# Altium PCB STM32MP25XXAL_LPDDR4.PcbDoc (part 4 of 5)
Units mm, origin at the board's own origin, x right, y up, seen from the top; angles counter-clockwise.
Board outline 125 x 95 mm, 6 copper layers (Top Layer, Signal Layer 1, Signal Layer 2, Signal Layer 3, Signal Layer 4, Bottom Layer), stack 1.403 mm thick; 182 components, 297 nets, 1131 pads, 958 vias.
Unrouted connection lines stored in the file: 5.
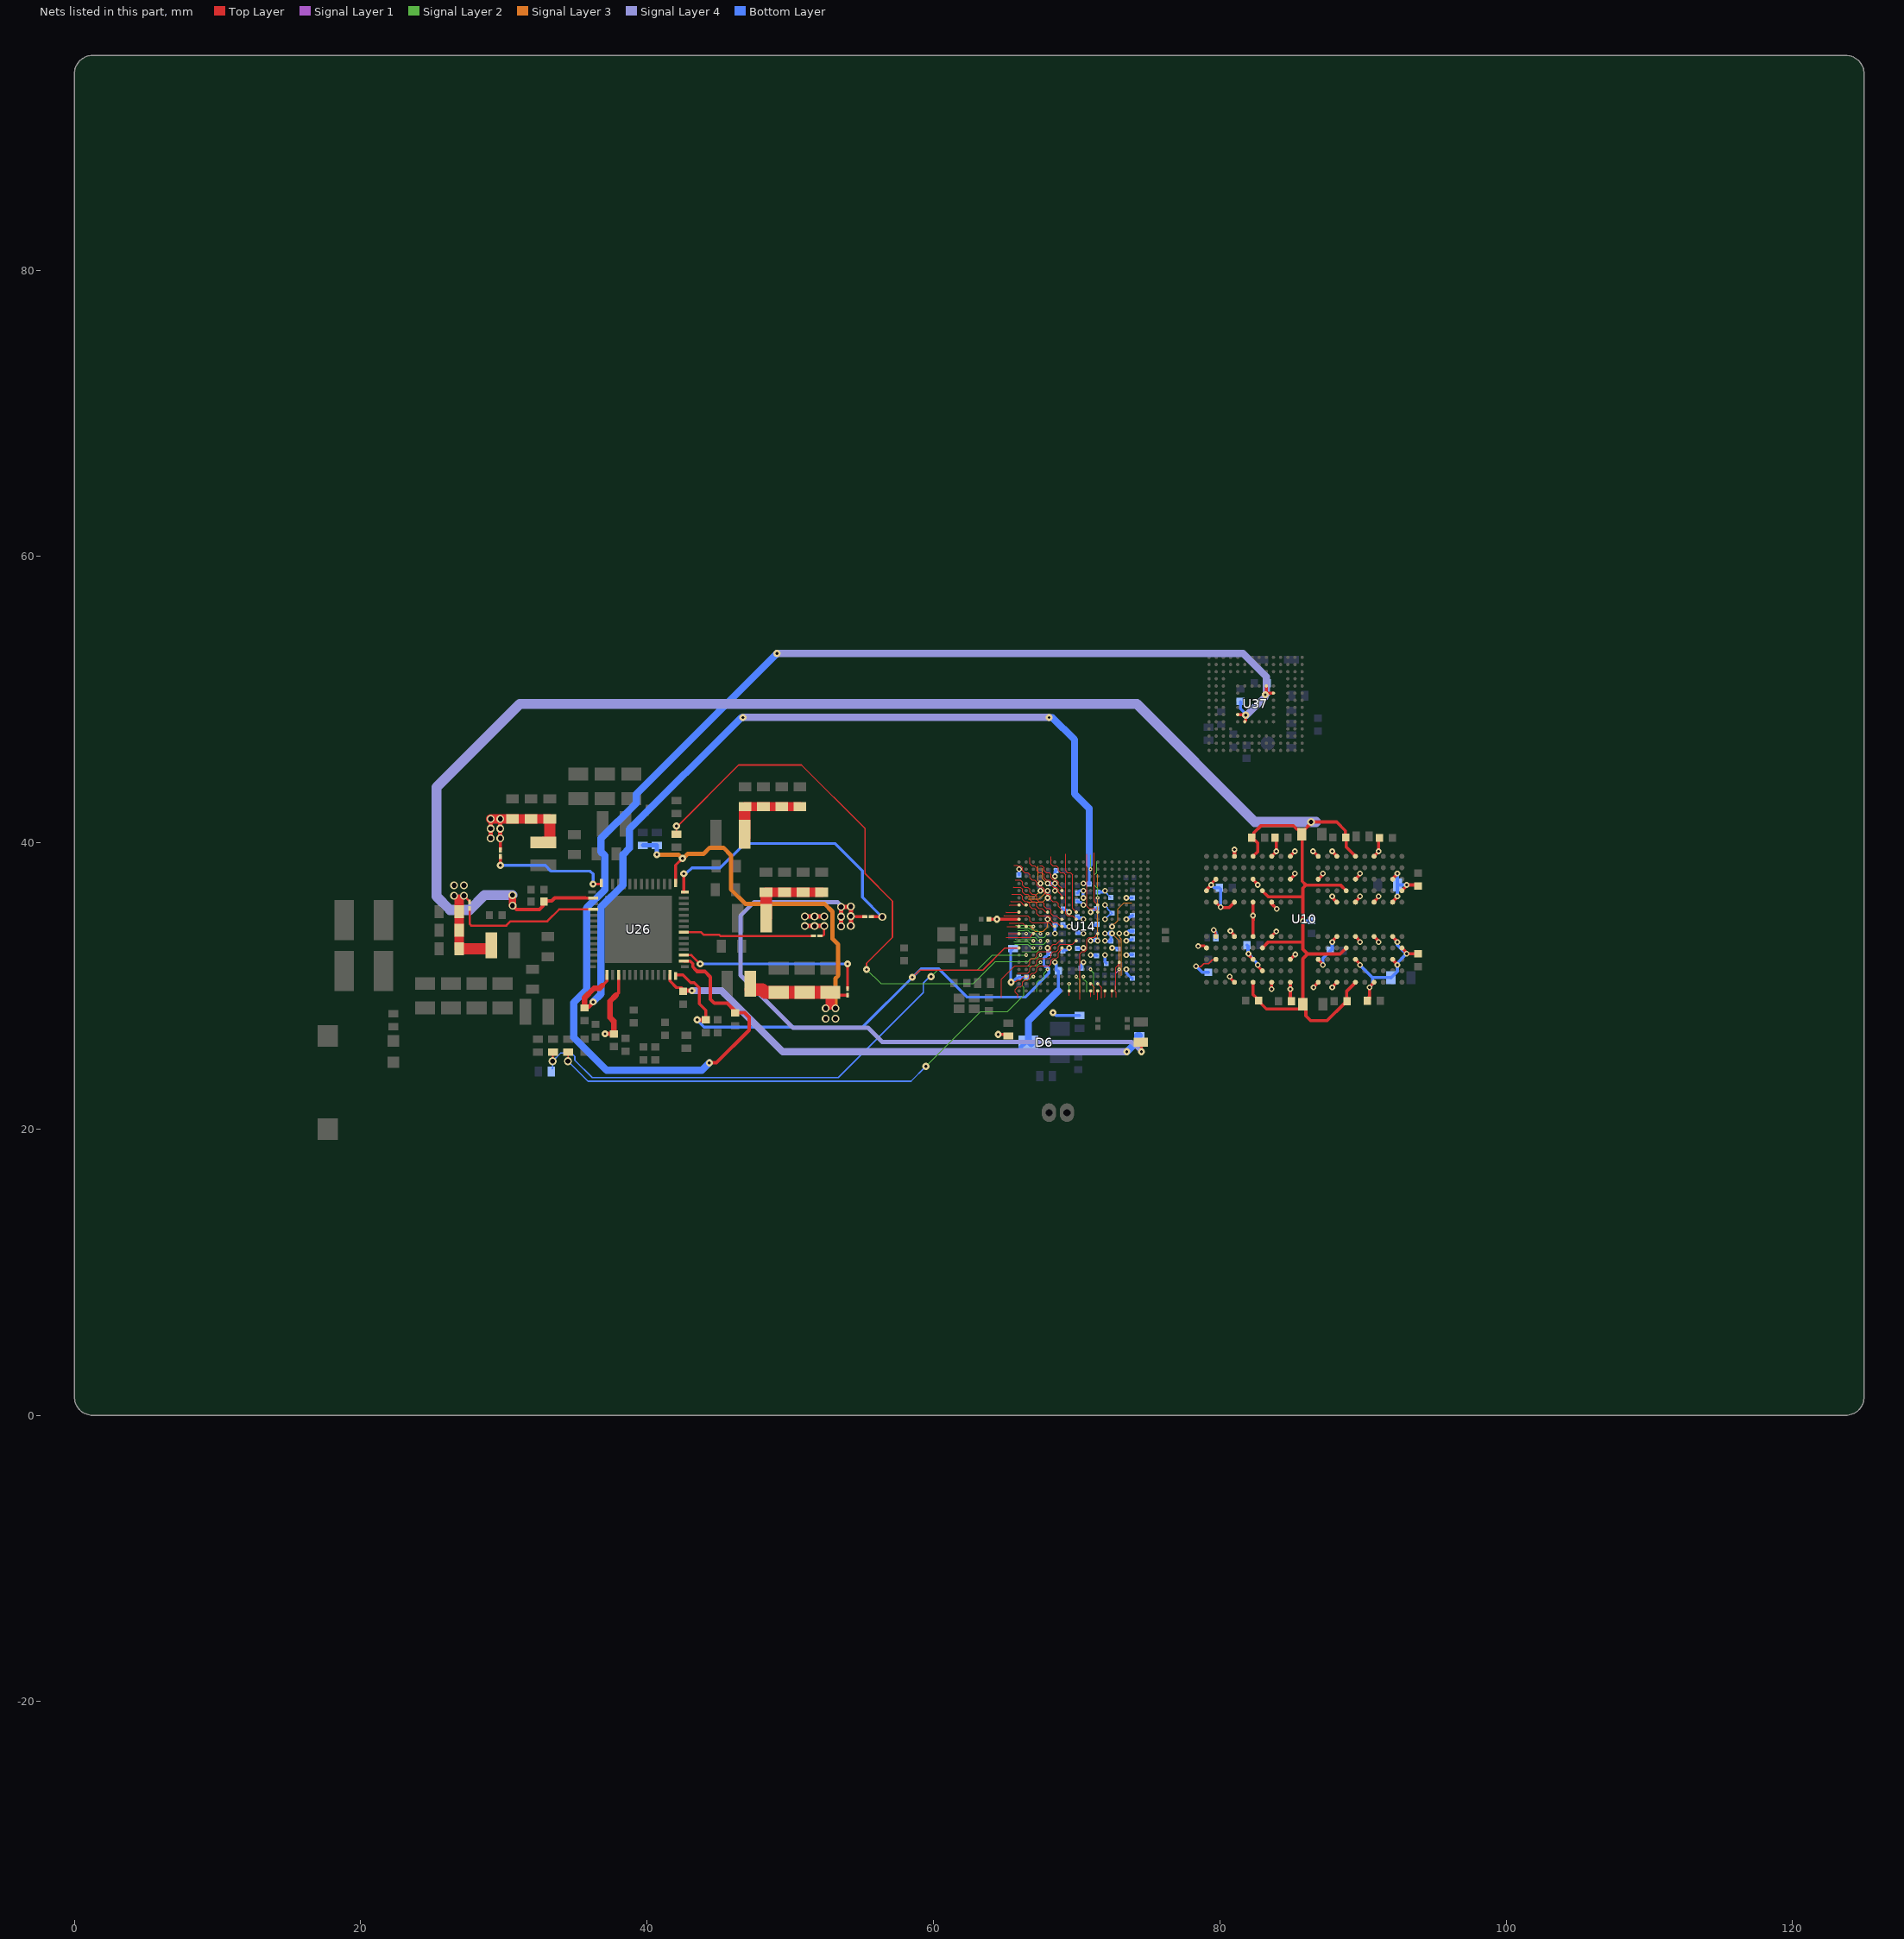
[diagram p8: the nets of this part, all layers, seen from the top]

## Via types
v1: diameter 0.26, hole 0.1, Top Layer to Signal Layer 1, 266 vias
v2: diameter 0.5, hole 0.2, Top Layer to Bottom Layer, 216 vias
v3: diameter 0.26, hole 0.1, Signal Layer 1 to Signal Layer 2, 138 vias
v4: diameter 0.4, hole 0.2, Signal Layer 1 to Signal Layer 4, 99 vias
v5: diameter 0.4, hole 0.2, Top Layer to Bottom Layer, tented both sides, 94 vias
v6: diameter 0.26, hole 0.1, Signal Layer 4 to Bottom Layer, 82 vias
v7: diameter 0.55, hole 0.35, Top Layer to Bottom Layer, 55 vias
v8: diameter 0.55, hole 0.3, Top Layer to Bottom Layer, 7 vias
v9: diameter 0.5, hole 0.2, Signal Layer 1 to Signal Layer 4, 1 vias

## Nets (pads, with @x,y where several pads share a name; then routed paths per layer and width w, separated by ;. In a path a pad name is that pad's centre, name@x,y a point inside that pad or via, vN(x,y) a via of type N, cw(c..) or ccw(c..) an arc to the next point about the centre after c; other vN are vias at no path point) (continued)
PG0: U14.T5 | length 2
  Signal Layer 2 w0.075: 67.226,29.601 67.226,30.253 67.373,30.401 67.578,30.401 67.726,30.548 67.726,30.901 v3(67.975,31.15)
  other v1: 67.975,31.15
PG1: U14.R4 | length 1.8
  Signal Layer 2 w0.075: 65.799,31.401 67.226,31.401 v3(67.475,31.65)
  other v1: 67.475,31.65
PG2: U14.M7 | length 7
  Top Layer w0.075: 64.75,29.159 64.75,30.458 65.692,31.4 66.575,31.4 66.725,31.55 66.725,31.764 ; 66.736,31.764 66.736,31.786 66.851,31.901 67.078,31.901 67.225,32.048 67.225,32.253 67.372,32.4 68.078,32.4 68.225,32.547 68.225,32.753 68.372,32.899 68.58,32.899 68.816,33.135 68.96,33.135 U14.M7@68.975,33.15
PG3: U14.H12 | length 4.6
  Top Layer w0.075: 70.725,39.199 70.725,35.547 70.872,35.401 71.224,35.401 U14.H12@71.475,35.15
PG4: U14.N7 | length 5.8
  Top Layer w0.075: 65.9,29.175 65.9,29.372 65.725,29.547 65.725,29.753 65.88,29.907 66.075,29.907 66.226,30.058 66.226,30.253 66.38,30.407 66.575,30.407 66.718,30.55 66.718,30.561 66.722,30.566 66.722,30.75 66.872,30.9 67.078,30.9 67.225,31.047 67.225,31.253 67.372,31.4 67.637,31.4 67.64,31.397 67.828,31.397 67.831,31.4 68.077,31.4 68.225,31.547 68.225,31.753 68.372,31.899 68.577,31.899 68.724,32.047 68.724,32.313 68.889,32.478 68.889,32.529 68.975,32.614 U14.N7@68.975,32.65
PG5: U14.K1 | length 0.8
  Top Layer w0.075: 65.15,34.15 U14.K1@65.975,34.15
PG6: U14.K2 | length 1.3
  Top Layer w0.075: 65.282,34.393 66.232,34.393 U14.K2@66.475,34.15
PG7: U14.E7 | length 2.7
  Top Layer w0.075: 67.421,38.4 67.422,38.399 67.578,38.399 67.725,38.253 67.725,38.047 67.872,37.9 68.078,37.9 68.225,37.752 68.225,37.547 68.373,37.399 68.578,37.399 68.732,37.245 68.732,37.05 68.963,36.819 68.963,36.704 U14.E7@68.993,36.674
PG8: U14.E5 | length 1.6
  Signal Layer 3 w0.075: 66.614,36.083 67.408,36.083 v4(67.975,36.65)
  other v1: 67.975,36.65
PG9: U14.G2 | length 1.2
  Top Layer w0.075: 65.375,35.925 65.407,35.893 66.075,35.893 66.218,35.75 66.218,35.707 66.25,35.675 66.275,35.65 U14.G2@66.475,35.65
PG10: U14.F5 | length 1.5
  Signal Layer 3 w0.075: 66.565,35.868 67.647,35.868 67.928,36.15 v4(67.975,36.15)
  other v1: 67.975,36.15
PG11: U14.F7 | length 4.2
  Top Layer w0.075: 66.725,38.962 66.725,38.547 66.872,38.4 66.874,38.4 66.875,38.399 67.078,38.399 67.224,38.253 67.224,38.048 67.372,37.901 67.577,37.901 67.725,37.752 67.725,37.547 67.872,37.4 68.078,37.4 68.225,37.253 68.225,37.05 68.225,37.047 68.372,36.901 68.374,36.901 68.376,36.899 68.578,36.899 68.732,36.745 68.732,36.55 68.955,36.327 68.955,36.212 U14.F7@68.993,36.174
PG12: U14.H7 | length 5.5
  Top Layer w0.075: 65.625,38.425 65.839,38.425 65.863,38.4 66.077,38.4 66.226,38.252 66.226,38.047 66.373,37.9 66.578,37.9 66.725,37.753 66.725,37.547 66.872,37.4 67.078,37.4 67.225,37.253 67.225,37.047 67.372,36.901 67.577,36.901 67.725,36.753 67.725,36.547 67.872,36.4 68.078,36.4 68.224,36.253 68.224,36.001 68.326,35.899 68.578,35.899 68.732,35.745 68.732,35.55 68.96,35.322 68.96,35.165 U14.H7@68.973,35.152
PG13: U14.J7 | length 5
  Top Layer w0.075: 65.7,37.4 65.871,37.4 65.872,37.399 66.078,37.399 66.225,37.252 66.225,37.047 66.373,36.9 66.578,36.9 66.725,36.753 66.725,36.547 66.872,36.4 67.078,36.4 67.225,36.252 67.225,36.047 67.372,35.9 67.578,35.9 67.726,35.752 67.726,35.547 67.872,35.4 68.078,35.4 68.225,35.253 68.225,35.047 68.372,34.901 68.584,34.901 68.806,34.678 68.947,34.678 U14.J7@68.975,34.65
PG14: U14.H5 | length 3.5
  Top Layer w0.075: 65.55,36.925 65.576,36.899 66.078,36.899 66.225,36.753 66.225,36.547 66.372,36.4 66.578,36.4 66.725,36.253 66.725,36.047 66.872,35.9 67.078,35.9 67.225,35.753 67.225,35.546 67.372,35.4 67.578,35.4 67.816,35.162 67.963,35.162 U14.H5@67.975,35.15
PG15: U14.E4 | length 1.2
  Signal Layer 3 w0.075: 66.475,36.25 67.075,36.25 v4(67.475,36.65)
  other v1: 67.475,36.65
PH2: U14.L14 | length 3.1
  Signal Layer 3 w0.075: v4(72.475,33.65) 72.975,33.15 72.975,30.78
  other v1: 72.475,33.65
PH3: U14.K14 | length 2.5
  Signal Layer 3 w0.075: v4(72.475,34.15) 72.475,34.159 72.875,34.559 72.875,35.375 73.3,35.8 73.853,35.8
  other v1: 72.475,34.15
PH4: U14.G12 | length 3.8
  Top Layer w0.075: 71.226,39.299 71.226,35.899 U14.G12@71.475,35.65
PH5: U14.M9 | length 5.5
  Top Layer w0.075: 65.875,30.9 66.578,30.9 66.725,31.047 66.725,31.253 66.872,31.4 67.077,31.4 67.224,31.547 67.224,31.65 ; 67.226,31.65 67.226,31.753 67.372,31.899 68.077,31.899 68.224,32.047 68.224,32.252 68.372,32.399 68.577,32.399 68.724,32.547 68.724,32.746 68.879,32.901 69.725,32.901 U14.M9@69.975,33.15
PH6: U14.L15 | length 3
  Signal Layer 3 w0.075: v4(72.975,33.65) 73.008,33.617 73.008,33.392 73.136,33.264 ; 73.137,30.714 73.137,33.264
  other v1: 72.975,33.65
PH7: U14.L12 | length 5.5
  Top Layer w0.075: 70.225,29.05 70.241,29.066 70.241,29.541 70.226,29.557 70.226,30.475 70.226,31.363 70.225,31.364 70.225,32.252 70.371,32.399 70.577,32.399 70.724,32.546 70.724,32.752 70.725,32.753 70.725,33.252 70.873,33.399 71.225,33.399 U14.L12@71.475,33.65
PH8: U14.M12 | length 4.6
  Signal Layer 3 w0.075: v4(71.475,33.15) 71.475,37.775
  other v1: 71.475,33.15
PH9: U14.W8 | length 0.3
  Top Layer w0.075: 69.475,29.325 U14.W8@69.475,29.65
PH10: U14.U10 | length 1.2
  Signal Layer 2 w0.075: v1(70.475,30.65) 70.475,30.443 70.519,30.399 70.578,30.399 70.724,30.253 70.724,29.566
  other v3: 70.475,30.65
PH11: U14.T11 | length 1.7
  Signal Layer 2 w0.075: v3(70.975,31.15) 70.975,31.1 71.2,30.875 71.2,29.518
  other v1: 70.975,31.15
PH12: U14.V8 | length 0.6
  Signal Layer 2 w0.075: 69.475,29.6 v3(69.475,30.15)
  other v1: 69.475,30.15
PH13: U14.U9 | length 1.2
  Signal Layer 2 w0.075: v3(69.975,30.65) 70.225,30.4 70.225,29.572
  other v1: 69.975,30.65
PI0: U14.H1 | length 0.9
  Top Layer w0.075: 65.05,35.175 65.075,35.15 U14.H1@65.975,35.15
PI1: U14.J9 | length 5.6
  Top Layer w0.075: 68.2,39.035 68.2,38.778 68.224,38.753 68.224,38.501 68.326,38.399 68.578,38.399 68.728,38.25 68.728,38.054 68.877,37.905 69.073,37.905 69.224,37.753 69.224,35.048 69.372,34.901 69.724,34.901 U14.J9@69.975,34.65
PI2: U14.J5 | length 2.6
  Signal Layer 3 w0.075: 66.175,34.225 66.675,34.225 67.091,33.809 67.663,33.809 67.975,34.121 v4(67.975,34.65)
  other v1: 67.975,34.65
PI3: U14.H9 | length 4.5
  Top Layer w0.075: 69.226,39.197 69.226,38.047 69.372,37.9 69.578,37.9 69.724,37.753 69.724,35.4 U14.H9@69.975,35.15
PI4: U14.G1 | length 0.7
  Top Layer w0.075: 65.325,35.625 65.35,35.65 U14.G1@65.975,35.65
PI5: U14.K7 | length 4.9
  Top Layer w0.075: 65.476,36.399 66.078,36.399 66.226,36.252 66.226,36.047 66.38,35.892 66.575,35.892 66.718,35.75 66.718,35.739 66.722,35.734 66.722,35.55 66.872,35.4 67.078,35.4 67.225,35.253 67.225,35.047 67.372,34.901 68.077,34.901 68.224,34.753 68.224,34.55 68.249,34.526 68.249,34.524 68.372,34.401 68.649,34.401 68.87,34.18 68.945,34.18 U14.K7@68.975,34.15
PI6: U14.D4 | length 1.3
  Signal Layer 3 w0.075: 67.323,38.375 67.323,37.356 67.475,37.204 v4(67.475,37.15)
  other v1: 67.475,37.15
PI7: U14.D5 | length 1.2
  Signal Layer 3 w0.075: 67.625,38.225 67.625,37.5 v4@67.975,37.15
  other v1: 67.975,37.15
  other v4: 67.975,37.15
PI8: U14.N4 | length 1.4
  Signal Layer 2 w0.075: 66.2,32.4 67.225,32.4 v3(67.475,32.65)
  other v1: 67.475,32.65
PI9: U14.K6 | length 4
  Top Layer w0.075: 64.9,34.925 64.926,34.899 66.578,34.899 66.724,34.753 66.724,34.575 66.726,34.574 66.726,34.547 66.872,34.401 68.078,34.401 68.316,34.162 68.463,34.162 U14.K6@68.475,34.15
PI10: U14.B11 | length 1
  Signal Layer 2 w0.075: v3(70.975,38.15) 70.975,39.15
  other v1: 70.975,38.15
PI11: U14.F12 | length 2.7
  Signal Layer 2 w0.075: 71.395,38.656 71.395,37.923 71.226,37.753 71.226,37.047 71.475,36.797 v3(71.475,36.15)
  other v1: 71.475,36.15
PMIC_WAKEUPn: R46.1 U14.P4 | length 42.1
  Top Layer w0.1: R46.1@42.048,40.587 42.048,41.081 46.399,45.432 50.777,45.432 55.214,40.995 55.214,37.847 57.138,35.924 57.138,33.388 55.328,31.578 v2(55.328,31.139)
  Signal Layer 2 w0.075: v2@55.325,31.15 56.325,30.15 62.775,30.15 64.34,31.715 66.616,31.715 66.801,31.899 67.225,31.899 v3(67.475,32.15)
  other v1: 67.475,32.15
  other v2: 42.048,41.172
PWR_CPU_ON: R60.1 R272.2 U14.P2 | length 39.3
  Top Layer w0.1: v7(33.398,24.739) 33.412,24.753 33.412,25.368 R60.1@33.428,25.384
  Signal Layer 2 w0.075: v2(59.825,30.65) 60.275,31.1 63.05,31.1 64.1,32.15 v1(66.475,32.15)
  Bottom Layer w0.1: R272.2@33.37,24.205 33.399,24.234 v7@33.399,24.737 ; v7(33.398,24.739) 33.959,25.3 34.725,25.3 34.95,25.075 34.95,24.8 36.166,23.584 53.344,23.584 59.297,29.537 59.297,30.197 v2@59.8,30.7
  other v3: 66.475,32.15
PWR_ON: R2.1 U14.U3 | length 37.4
  Top Layer w0.1: v7(34.473,24.739) 34.478,24.744 R2.1@34.478,25.384
  Signal Layer 2 w0.075: v2(59.475,24.375) 63.3,28.2 65.175,28.2 66.325,29.35 66.325,29.87 66.226,29.97 66.226,30.282 66.369,30.425 66.664,30.425 66.804,30.566 66.84,30.566 66.925,30.65 v3(66.975,30.65)
  Bottom Layer w0.1: v7(34.473,24.739) 35.878,23.334 58.434,23.334 v2(59.475,24.375)
  other v1: 66.975,30.65
PZ0: U14.L5 | length 2.4
  Signal Layer 2 w0.075: 65.894,33.875 66.347,33.875 66.372,33.899 66.578,33.899 66.742,33.736 66.839,33.736 66.875,33.7 67.072,33.7 67.372,33.4 67.726,33.4 v3(67.975,33.65)
  other v1: 67.975,33.65
PZ1: U14.M4 | length 1.8
  Signal Layer 2 w0.075: 65.825,33.4 67.078,33.4 67.087,33.391 67.292,33.185 67.44,33.185 v3(67.475,33.15)
  other v1: 67.475,33.15
PZ2: U14.M3 | length 1.3
  Signal Layer 2 w0.075: 65.71,33.281 65.722,33.281 65.76,33.243 66.794,33.243 66.852,33.185 66.94,33.185 v3(66.975,33.15)
  other v1: 66.975,33.15
PZ3: U14.M5 | length 2.5
  Signal Layer 2 w0.075: 65.625,33.075 66.625,33.075 66.799,32.901 67.703,32.901 67.953,33.15 v3(67.975,33.15)
  other v1: 67.975,33.15
PZ4: U14.L4 | length 1.8
  Signal Layer 2 w0.075: 65.868,34.04 66.279,34.04 66.303,34.064 66.647,34.064 66.711,34 66.772,34 66.872,33.901 67.224,33.901 v3(67.475,33.65)
  other v1: 67.475,33.65
PZ5: U14.N3 | length 1.4
  Signal Layer 2 w0.075: 65.678,32.9 66.578,32.9 66.724,32.753 66.724,32.749 66.803,32.671 66.954,32.671 v3(66.975,32.65)
  other v1: 66.975,32.65
PZ6: U14.K3 | length 1.3
  Signal Layer 2 w0.075: 65.755,34.225 66.23,34.225 66.235,34.229 66.715,34.229 66.72,34.225 66.85,34.225 66.925,34.15 v3(66.975,34.15)
  other v1: 66.975,34.15
PZ7: U14.L1 | length 0.8
  Top Layer w0.075: 65.225,33.65 U14.L1@65.975,33.65
PZ8: U14.L3 | length 2
  Top Layer w0.075: 65.083,33.4 66.725,33.4 U14.L3@66.975,33.65
PZ9: U14.L2 | length 0.5
  Signal Layer 2 w0.075: 65.95,33.65 v3(66.475,33.65)
  other v1: 66.475,33.65
UCPD1_CC1: U14.W13 | length 0.4
  Top Layer w0.075: 71.95,29.225 71.975,29.25 U14.W13@71.975,29.65
UCPD1_CC2: U14.W14 | length 0.5
  Top Layer w0.075: 72.475,29.2 U14.W14@72.475,29.65
USB3DR_DM: U14.V12 | length 1.1
  Top Layer w0.075: U14.V12@71.475,30.15 71.725,29.9 71.725,29.125
USB3DR_DP: U14.W12 | length 0.6
  Top Layer w0.075: 71.45,29.05 71.475,29.075 U14.W12@71.475,29.65
USB3DR_TXRTUNE: U14.R15 | length 2.6
  Top Layer w0.075: 72.775,29.203 72.775,29.518 72.71,29.584 72.71,30.032 72.725,30.047 72.725,31.274 72.952,31.502 72.952,31.627 U14.R15@72.975,31.65
USBH_HS_DM: U14.V11 | length 0.9
  Top Layer w0.075: U14.V11@70.975,30.15 71.225,29.9 71.225,29.375
USBH_HS_DP: U14.W11 | length 0.4
  Top Layer w0.075: 70.975,29.225 U14.W11@70.975,29.65
USBH_HS_TXRTUNE: U14.T15 | length 1.5
  Signal Layer 1 w0.075: 72.725,29.75 72.725,30.9 v1(72.975,31.15)
VBAT: C87.2 D6.3 U14.R6 | length 7.3
  Bottom Layer w0.2: v6(68.475,31.65) 68.475,31.634 68.575,31.534 C87.2@68.575,31.1 ; 68.725,29.654 C87.2@68.725,31.05
  Bottom Layer w0.3: D6.3@66.076,25.692 66.426,26.042 D6.3@66.626,26.042
  Bottom Layer w0.5: D6.3@66.825,25.975 66.626,26.174 66.626,27.555 68.725,29.654
  other v1: 68.475,31.65
  other v4: 68.475,31.65
VDD1_DDR: C40.2 C62.2 C63.2 C64.2 C65.2 C66.2 C67.2 C68.2 U10.F1 U10.F12 U10.G4 U10.G9 U10.T4 U10.T9 U10.U1 U10.U12 U26.44 | length 135.6
  Top Layer w0.15: U10.F12@82.325,39.05 U10.F12@82.34,39.066
  Top Layer w0.21: 35.673,36.139 U26.44@36.228,36.139
  Top Layer w0.22: U10.F1@82.325,30.25 82.325,29.393 82.555,29.163 82.555,29.09 83.26,28.385 85.59,28.385 C63.2@85.8,28.595 ; U10.F12@82.325,39.05 82.65,39.375 82.65,39.975 82.445,40.18 82.387,40.18 82.3,40.267 82.387,40.354 82.387,40.697 82.875,41.185 85.15,41.185 85.415,40.92 85.539,40.92 C62.2@85.75,40.71 ; U10.G9@82.95,36.65 83.37,36.23 85.8,36.23 ; U10.G4@82.975,32.65 83.39,33.065 85.8,33.065 ; C63.2@85.8,28.582 C63.2@85.8,28.72 85.8,31.891 86.138,32.229 ; C63.2@85.812,28.582 86.01,28.385 86.01,27.899 86.323,27.586 86.323,27.58 87.502,27.58 88.688,28.765 88.755,28.765 88.871,28.881 C67.2@88.871,28.973 ; U10.T4@88.825,32.65 88.404,32.229 86.125,32.229 85.8,32.555 85.8,33.065 ; U10.T9@88.825,36.65 88.429,37.046 86.014,37.046 ; C67.2@89.016,29.118 C67.2@88.871,28.973 ; U10.U1@89.475,30.25 89.475,30.245 88.871,29.641 C67.2@88.871,28.973 ; U10.U12@89.475,39.056 88.825,39.706 88.825,40.36 88.768,40.416 88.768,40.841 88.16,41.45 v8(86.375,41.45) 86.312,41.387 86.312,41.297 85.935,40.92 85.75,40.735 C62.2@85.75,40.71 ; C62.2@85.75,40.71 85.75,37.31 86.014,37.046 ; 85.8,33.065 85.8,36.831 86.014,37.046
  Top Layer w0.25: v7(30.6,35.612) 30.873,35.339 32.473,35.339 32.718,35.584 32.718,35.774 32.833,35.889 C40.2@32.903,35.889 ; C40.2@32.908,35.774 33.063,35.929 33.338,35.929 33.548,36.139 35.673,36.139
  Top Layer w0.5: v7(30.6,35.612) v7@30.6,36.335
  Signal Layer 4 w0.7: v7(30.598,36.337) 28.644,36.337 27.608,35.301 26.236,35.301 25.282,36.255 25.282,43.871 31.098,49.687 74.213,49.687 82.45,41.45 86.725,41.45
  Bottom Layer w0.22: v5(85.8,34.525) C68.2@86.425,34.525
VDD2_DDR: C41.2 C50.2 C51.2 C52.2 C53.1 C54.1 C55.1 C56.1 C57.1 C58.1 C59.1 C60.1 C61.1 C175.1 C192.1 C200.2 C202.2 C211.1 C284.1 C304.1 C306.1 L5.2 LNK8.2 R94.2 U10.A4 U10.A9 U10.AA3 U10.AA5 U10.AA8 U10.AA10 U10.AB4 U10.AB9 U10.B3 U10.B5 U10.B8 U10.B10 U10.D1 U10.D5 U10.D8 U10.D12 U10.F3 U10.F5 U10.F8 U10.F10 U10.G2 U10.H1 U10.H5 U10.H8 U10.H12 U10.K1 U10.K3 U10.K10 U10.K12 U10.N1 U10.N3 U10.N10 U10.N12 U10.R1 U10.R5 U10.R8 U10.R12 U10.U3 U10.U5 U10.U8 U10.U10 U10.W1 U10.W5 U10.W8 U10.W12 U14.F16 U14.J16 U14.L16 U14.M16 U14.P16 U14.T16 | length 56
  Top Layer w0.09: v5(78.35,31.375) 78.375,31.35 78.681,31.35 78.872,31.54 79.203,31.54 79.49,31.827 79.701,31.827 U10.B3@79.725,31.85
  Top Layer w0.15: v7(27.196,36.304) 27.598,35.902 LNK8.2@27.598,35.862 ; v5@79.575,33.925 79.575,33.857 79.686,33.746 79.686,33.488 U10.B5@79.725,33.45
  Top Layer w0.2: v5(78.5,32.775) 78.529,32.804 78.882,32.804 79.036,32.65 U10.A4@79.075,32.65 ; v5(80.7,30.65) 80.7,30.575 U10.D1@81.025,30.25 ; U10.H5@83.625,33.45 83.625,33.475 v5(83.95,33.8)
  Top Layer w0.22: U10.A9@79.09,36.665 U10.A9@79.075,36.65 79.075,36.725 79.4,37.05 79.4,37.125 U10.B10@79.725,37.45 U10.B10@79.725,37.445 ; U10.B8@79.725,35.83 v5@80.025,35.53 ; v5@80.025,35.51 80.059,35.476 80.219,35.476 80.65,35.475 U10.D8@81.025,35.85 ; v5@80.733,33.831 80.96,33.604 80.96,33.55 81.025,33.485 U10.D5@81.025,33.45 ; v5@82,32.17 82.32,31.85 U10.F3@82.325,31.85 ; U10.F5@82.325,33.45 82.325,34.576 82.337,34.588 82.337,34.898 v5(82.325,34.91) U10.F8@82.325,35.85 ; U10.F10@82.325,37.45 82.325,37.421 82.64,37.105 v5@82.64,37.07 ; v5(82.65,31.45) 82.684,31.416 82.684,31.341 U10.G2@82.975,31.05 ; v5@83.6,29.76 83.625,29.785 U10.H1@83.625,30.25 ; U10.H8@83.625,35.81 83.625,35.725 v5(83.975,35.375) ; U10.H12@83.625,39.05 83.95,39.375 83.95,40.25 C52.2@83.85,40.35 ; v5(84.925,29.77) 84.925,29.01 C54.1@85,28.935 ; v5@84.925,29.775 U10.K1@84.925,30.25 ; U10.K10@84.925,37.45 84.93,37.45 85.25,37.77 v5@85.25,37.785 ; U10.K12@84.925,39.05 84.925,39.075 v5(85.25,39.4) ; U10.K3@84.925,31.85 v5(85.275,32.2) ; v5@86.477,39.448 U10.N12@86.875,39.05 ; v5@86.55,29.92 86.875,30.245 U10.N1@86.875,30.25 ; U10.N3@86.875,31.833 87.165,31.543 87.165,31.485 v5(87.2,31.45) ; U10.N10@86.875,37.45 86.88,37.45 v5@87.2,37.77 ; v5@87.85,29.92 88.175,30.245 U10.R1@88.175,30.25 ; v5@87.85,33.12 88.175,33.445 U10.R5@88.175,33.45 ; v5(87.85,36.25) 87.884,36.216 87.884,36.141 U10.R8@88.175,35.85 ; v5(87.85,39.4) 88.175,39.075 U10.R12@88.175,39.05 ; U10.U3@89.474,31.845 89.765,31.554 89.765,31.485 v5(89.8,31.45) ; U10.U5@89.475,33.45 89.8,33.125 v5@89.8,33.12 ; U10.U8@89.475,35.85 89.475,35.885 89.54,35.95 89.54,35.953 89.8,36.213 v5(89.8,36.25) ; U10.U10@89.475,37.45 89.48,37.45 v5@89.8,37.77 ; C55.1@90.3,28.95 90.445,29.095 90.445,29.244 90.45,29.249 v5(90.45,29.9) 90.45,29.92 U10.W1@90.775,30.245 ; U10.W1@90.775,30.238 U10.W1@90.775,30.245 ; U10.W1@90.775,30.25 U10.W1@90.775,30.245 ; U10.W5@90.775,33.45 90.775,33.445 v5@91.1,33.12 ; U10.W8@90.775,35.87 91.065,36.161 91.065,36.216 v5(91.1,36.25) ; U10.W12@90.775,39.05 91.095,39.37 v5@91.1,39.37 ; v5(91.1,39.4) C53.1@91.1,40.23 ; U10.AA3@92.075,31.85 92.075,31.823 92.4,31.498 v5(92.4,31.45) ; U10.AA5@92.075,33.45 92.075,33.422 92.4,33.097 v5(92.4,33.05) ; U10.AA8@92.075,35.85 92.075,35.884 92.4,36.209 v5(92.4,36.25) ; U10.AA10@92.075,37.45 92.075,37.485 92.4,37.81 v5(92.4,37.85) ; U10.AB4@92.725,32.65 92.965,32.41 92.965,32.322 v5@93.034,32.253 ; U10.AB9@92.725,36.65 93.015,36.941 93.015,37.016 v5(93.05,37.05) 93.77,37.05 C56.1@93.85,36.97 ; v5@93.052,32.248 C57.1@93.836,32.248
  Top Layer w0.28: U10.D12@81.025,39.05 v5@81.025,39.5
  Top Layer w0.64: C202.2@26.873,32.589 C41.2@26.873,33.889 C200.2@26.873,35.189 ; 26.873,35.634 26.873,36.064
  Top Layer w0.8: C202.2@27.098,32.589 L5.2@28.873,32.589
  Bottom Layer w0.2: v4(73.475,31.15) 73.475,30.875 73.75,30.6 73.825,30.6 C284.1@73.9,30.525 C284.1@73.9,30.45 ; v4(73.475,33.15) 73.491,33.15 73.551,33.209 73.834,33.209 C306.1@73.9,33.275 ; v4(73.475,36.15) C304.1@73.9,36.15
  Bottom Layer w0.22: v4(73.475,32.15) 73.5,32.175 C192.1@73.9,32.175 ; v4(73.475,33.65) 73.65,33.825 C211.1@73.9,33.825 C211.1@73.925,33.825 ; v1(73.475,34.65) 73.486,34.65 73.576,34.74 73.593,34.74 73.603,34.75 73.655,34.75 73.765,34.86 73.835,34.86 C175.1@73.9,34.925 ; v5(78.35,31.375) 78.775,30.95 C60.1@79.2,30.95 ; v5(79.4,37.05) 79.6,36.85 C61.1@79.975,36.85 80.054,36.771 v5@80.054,35.504 ; v5(79.57,33.9) 79.725,33.745 R94.2@79.725,33.35 R94.2@79.725,33.325 ; C59.1@81.9,32.85 81.975,32.775 v5@81.975,32.225 ; v5(82,32.25) 82.23,32.02 82.23,31.976 82.56,31.647 82.56,31.589 82.65,31.499 v5(82.65,31.45) ; v5(87.2,31.45) 87.2,31.925 C58.1@87.725,32.45 C58.1@87.75,32.475 ; C58.1@87.75,32.45 87.85,32.55 v5(87.85,33.05) ; v5(89.8,31.45) 90.675,30.575 ; v5@90.45,29.9 90.675,30.125 90.675,30.575 ; 91.1,30.575 90.675,30.575 ; 91.125,30.575 C50.2@91.95,30.575 ; C50.2@91.95,30.55 92.4,31 v5(92.4,31.45) ; v5@92.35,31.45 92.35,31.551 v5@93.025,32.225 ; v5(92.4,33.05) 92.4,32.85 v5@93.025,32.225 ; v5(92.4,36.25) C51.2@92.4,37.075 ; v5(92.4,37.85) 92.4,37.15 C51.2@92.425,37.125 ; C51.2@92.425,37.1 92.475,37.05 v5(93.05,37.05) ; v5(93.05,32.25) v5@93.025,32.225
  other v1: 73.475,31.15 73.475,32.15 73.475,33.15 73.475,33.65 73.475,36.15
  other v4: 73.475,34.65
  other v5: 83.625,29.77 86.55,29.9 87.85,29.9 89.8,33.05 91.1,33.05 80.735,33.831 80.05,35.5 82.65,37.05 85.25,37.85 87.2,37.85 89.8,37.85 83.95,39.4 86.5,39.4 81.025,39.525
  other v6: 73.475,31.15 73.475,32.15 73.475,33.15 73.475,33.65 73.475,34.65 73.475,36.15
  other v7: 26.521,36.304 26.521,37.029 27.196,37.029
VDD3V3_USB: C156.2 R286.1 U26.13 | length 36
  Top Layer w0.21: U26.13@41.598,30.769 41.598,30.339 42.061,29.876 42.316,29.876 42.318,29.874 42.388,29.874 42.523,29.739 C156.2@42.523,29.669
  Top Layer w0.3: C156.2@42.523,29.669 v2(43.133,29.669)
  Signal Layer 4 w0.5: v2@43.134,29.668 45.207,29.668 49.475,25.4 v2(73.5,25.4)
  Bottom Layer w0.5: v2(73.5,25.4) 74.275,26.175 74.275,26.52 74.28,26.525 R286.1@74.375,26.525
VDD_DDR_FB: LNK8.1 U26.46 | length 10.2
  Top Layer w0.15: LNK8.1@27.598,35.412 27.598,34.329 27.715,34.212 30.165,34.212 30.465,34.512 31.135,34.512 31.137,34.514 33.025,34.514 33.85,35.339 U26.46@36.228,35.339
VDD_EMMC: C9.2 C117.2 C190.1 U26.16 U37.E6 U37.F5 U37.J10 U37.K9 | length 97.6
  Top Layer w0.2: U37.E6@81.25,48.95 v2@81.8,48.95 ; U37.F5@81.751,48.447 81.751,48.459 81.8,48.508 v2(81.8,48.915) ; v2(83.176,50.347) v2@83.251,50.422 ; U37.J10@83.251,50.947 83.251,50.517 83.243,50.509 83.243,50.43 v2@83.251,50.422 ; U37.K9@83.751,50.447 83.371,50.447 83.338,50.414 83.259,50.414 v2@83.251,50.422
  Top Layer w0.21: U26.16@42.568,31.739 42.998,31.739 43.186,31.551 43.186,31.326 43.332,31.18
  Top Layer w0.25: 43.33,31.177 43.496,31.011 44.026,31.011 44.423,30.614 44.423,29.064 44.698,28.789 45.593,28.789 46.148,28.234 C190.1@46.148,28.164 ; v2(44.35,24.625) 44.841,24.625 47.123,26.907 47.123,27.807 46.81,28.12 C190.1@46.164,28.12
  Signal Layer 4 w0.5: v2(49.075,53.225) 81.625,53.225 83.25,51.6 83.25,50.375 v2@83.2,50.325 ; v2(81.8,48.915) 81.888,48.915 83.176,50.203 v2(83.176,50.347)
  Bottom Layer w0.2: C9.2@81.451,49.863 81.451,49.357 v2@81.72,49.088 ; v2@83.186,50.338 83.186,51.023 C117.2@83.311,51.148
  Bottom Layer w0.5: v2(44.35,24.625) 43.825,24.1 37.182,24.1 34.875,26.407 34.875,28.825 35.775,29.725 35.775,35.445 37.054,36.724 37.054,39.096 36.775,39.375 36.775,40.309 39.252,42.786 39.252,43.402 v2(49.075,53.225)
VDD_SDCARD: C142.1 U26.4 | length 5.1
  Top Layer w0.21: 37.823,29.339 37.998,29.514 U26.4@37.998,30.769
  Top Layer w0.3: v2(37.063,26.649) C142.1@37.673,26.649
  Top Layer w0.4: C142.1@37.673,26.649 37.673,27.532 37.408,27.797 37.408,28.924 37.823,29.339
VDDA1V8_AON: C189.2 C234.2 U14.N1 U14.N5 U26.14 | length 43.6
  Top Layer w0.1: v2(58.525,30.6) 58.536,30.6 59.041,31.104 63.444,31.104 64.976,32.636 65.323,32.636 65.961,32.636 U14.N1@65.975,32.65
  Top Layer w0.21: U26.14@41.998,30.769 42.508,30.769 43.046,30.231 43.286,30.231 43.643,29.873 43.643,28.741 44.098,28.286 C189.2@44.098,27.629
  Top Layer w0.3: v2(43.488,27.629) C189.2@44.098,27.629
  Bottom Layer w0.2: v2@43.469,27.63 43.974,27.126 55.051,27.126 v2(58.525,30.6) 59.125,31.2 60.375,31.2 62.364,29.211 66.397,29.211 68.07,30.884 68.07,31.221 67.953,31.338 67.82,31.338 67.713,31.445 67.713,31.945 67.82,32.052 67.878,32.052 67.995,32.169 C234.2@68.07,32.245 ; v4(67.975,32.65) 67.975,32.35 67.995,32.33 67.995,32.32 C234.2@68.065,32.25
  other v1: 67.975,32.65
  other v6: 67.975,32.65
VDDCORE: C16.2 C22.2 C23.2 C24.2 C183.2 C195.1 C196.2 C201.2 C203.1 C213.2 C215.2 C289.2 C299.2 C300.2 L2.2 LNK2.2 R11.1 U14.B1 U14.C6 U14.G10 U14.H11 U14.J1 U14.J10 U14.K11 U14.L10 U14.N8 U14.N10 | length 58.9
  Top Layer w0.2: C22.2@50.673,42.514 C22.2@50.721,42.562 ; 54.598,34.839 LNK2.2@55.214,34.839 ; C201.2@63.9,34.65 v2(64.425,34.65) ; v2@64.425,34.625 64.45,34.65 U14.J1@65.975,34.65 ; R11.1@74.475,26.075 74.525,26.025 v2(74.525,25.4) v2@74.525,25.375
  Top Layer w0.3: v7(53.554,34.163) v7(53.554,34.838) v7(53.554,35.513) 54.229,35.513 v7@54.229,34.163
  Top Layer w0.64: C183.2@46.848,42.514 C24.2@48.123,42.514 C23.2@49.398,42.514 C22.2@50.673,42.514
  Top Layer w0.8: L2.2@46.813,40.339 L2.2@46.813,40.589 C183.2@46.813,42.312
  Signal Layer 4 w0.3: v7@53.6,35.55 53.3,35.85 47.475,35.85 46.516,34.891 46.516,30.747 50.187,27.075 55.425,27.075 56.42,26.08 73.845,26.08 v2(74.525,25.4)
  Bottom Layer w0.2: C215.2@65.975,37.75 v4(65.975,38.15) ; v4(68.475,37.65) 68.475,37.98 C16.2@68.55,38.055 ; C300.2@69.05,32.425 69.125,32.5 69.309,32.5 69.459,32.65 v1(69.475,32.65) ; C195.1@70.05,32.625 70.434,32.625 70.459,32.65 v1(70.474,32.649) ; C289.2@70.05,33.725 70.083,33.692 70.417,33.692 70.459,33.65 v1(70.475,33.65) ; C196.2@70.05,34.825 70.125,34.75 70.359,34.75 70.459,34.65 v1(70.475,34.65) ; C213.2@70.05,35.925 70.125,35.85 70.275,35.85 v1(70.475,35.65) ; v1(70.975,34.15) 70.991,34.15 71.073,34.232 71.327,34.232 C203.1@71.4,34.305 ; v1(70.975,35.15) 70.991,35.15 71.171,35.33 71.325,35.33 C299.2@71.4,35.405
  other v1: 68.475,37.65 65.975,38.15
  other v4: 69.475,32.65 70.474,32.649 70.475,33.65 70.975,34.15 70.475,34.65 70.975,35.15 70.475,35.65
  other v6: 69.475,32.65 70.474,32.649 70.475,33.65 70.975,34.15 70.475,34.65 70.975,35.15 70.475,35.65 68.475,37.65 65.975,38.15
  other v7: 54.224,34.193 54.224,34.868 54.224,35.543
VDDCORE_FB: LNK2.1 U26.28 | length 20.6
  Top Layer w0.2: U26.28@42.568,36.539 v2(42.568,37.839) ; LNK2.1@55.664,34.839 v7@56.274,34.839
  Bottom Layer w0.2: v2@42.544,37.837 42.601,37.894 42.775,37.894 43.128,38.248 45.108,38.248 46.801,39.941 53.147,39.941 55.049,38.039 55.049,36.178 v7@56.407,34.82 ; v2@42.549,37.84 42.606,37.898 42.78,37.898 43.133,38.251
  other v7: 56.431,34.822
VDDCPU: C26.2 C27.2 C28.2 C177.1 C191.1 C194.2 C283.2 C287.2 L3.2 LNK4.1 U14.E13 U14.G13 U14.J13 U14.L13 U14.M13 | length 14.1
  Top Layer w0.2: LNK4.1@29.748,39.489 v7(29.748,40.312)
  Top Layer w0.3: v7(29.073,40.312) v7(29.073,40.987) v7(29.073,41.662) v7(29.748,41.662) v7(29.748,40.987) v7(29.748,40.312)
  Top Layer w0.64: v7(29.073,41.662) 29.073,41.664 C27.2@30.598,41.664 C28.2@31.898,41.664 C26.2@33.198,41.664
  Top Layer w0.8: L3.2@32.748,40.014 33.198,40.014 33.198,41.312
  Bottom Layer w0.1: v1(71.975,34.65) 72.275,34.95 72.35,34.95 C177.1@72.475,35.075 ; v1(71.975,35.65) 72.168,35.457 72.168,35.382 C177.1@72.475,35.075 ; v6@71.977,36.65 71.977,36.605 72.065,36.517 72.065,36.492 72.255,36.302 72.255,36.3 C191.1@72.38,36.175 ; C177.1@72.475,35.05 C177.1@72.475,35.075
  Bottom Layer w0.2: C287.2@71.5,36.55 71.875,36.55 v1(71.975,36.65) ; v1(71.975,33.65) C194.2@72.4,33.65 ; v6@72,33.125 C283.2@72.4,33.125 ; C283.2@72.375,33.1 C283.2@72.4,33.125 ; C194.2@72.4,33.675 C194.2@72.4,33.65 ; C194.2@72.425,33.65 C194.2@72.4,33.65 ; C283.2@72.4,33.125 C194.2@72.4,33.65
  other v1: 71.975,33.15
  other v4: 71.975,33.15 71.975,33.65 71.975,34.65 71.975,35.65 71.975,36.65
  other v6: 71.975,33.15 71.975,33.65 71.975,34.65 71.975,35.65 71.975,36.65
VDDCPU_FB: LNK4.2 U26.42 | length 8.6
  Top Layer w0.2: v2(29.748,38.429) LNK4.2@29.748,39.039 ; v2(36.223,37.114) U26.42@36.793,37.114
  Bottom Layer w0.2: v2(29.748,38.429) 32.878,38.427 33.293,38.012 36.022,38.012 36.224,37.81 v2@36.224,37.112
VDDGPU: C1.2 C2.2 C3.2 C4.2 C5.2 C34.2 C35.2 C36.2 C37.2 L4.2 LNK7.2 U14.M11 U14.N14 U14.P11 U14.P13 U14.R10 | length 11.6
  Top Layer w0.15: LNK7.2@52.073,33.489 52.08,33.497 52.283,33.497 52.371,33.584 v7(52.371,34.177)
  Top Layer w0.2: C35.2@52.448,36.531 C35.2@52.496,36.484
  Top Layer w0.3: v7(51.021,34.177) v7(51.696,34.177) v7(52.371,34.177) ; v7(51.021,34.852) v7(51.696,34.852) v7(52.371,34.852)
  Top Layer w0.64: C37.2@48.298,36.539 C36.2@49.598,36.539 C34.2@50.898,36.539 C35.2@52.198,36.539
  Top Layer w0.8: L4.2@48.323,34.739 48.323,36.212
  Bottom Layer w0.2: C2.2@70.25,31.225 70.315,31.29 70.315,31.491 v1(70.474,31.65) ; v6(70.975,32.15) 71.355,32.15 C1.2@71.4,32.105 ; v1(70.975,33.149) 70.991,33.149 71.023,33.181 71.376,33.181 C3.2@71.4,33.205 ; v1(71.975,32.15) 71.975,31.675 C4.2@72.075,31.575 ; v1(72.475,32.65) 72.825,32.65 C5.2@72.9,32.575
  other v1: 70.975,32.15
  other v4: 70.474,31.65 70.975,32.15 71.975,32.15 72.475,32.65 70.975,33.149
  other v6: 70.474,31.65 71.975,32.15 72.475,32.65 70.975,33.149
VDDGPU_FB: LNK7.1 U26.21 | length 9.3
  Top Layer w0.15: U26.21@42.448,33.739 43.781,33.739 43.958,33.562 45.038,33.562 45.111,33.489 LNK7.1@51.623,33.489
VDDIO: C17.2 C19.2 C186.2 C187.2 C197.2 C205.2 C219.2 C307.1 L6.2 LNK11.2 R27.2 R67.2 R260.2 R261.2 U14.D6 U14.E6 U14.E10 U14.F10 U14.H8 U14.K8 U14.L6 U26.29 | length 40.2
  Top Layer w0.2: U26.29@41.998,37.184 41.998,38.437 v2(42.473,38.912) ; C186.2@52.798,29.539 52.983,29.354 LNK11.2@53.998,29.354 ; v2(64.525,26.6) 64.538,26.613 65.213,26.613 R27.2@65.225,26.625
  Top Layer w0.64: 52.798,28.664 C186.2@52.798,29.094
  Top Layer w0.9: L6.2@47.248,29.739 48.048,29.739 48.248,29.539 C187.2@49.198,29.539 C19.2@50.998,29.539 C186.2@52.798,29.539
  Signal Layer 3 w0.3: v2@40.683,39.165 42.198,39.165 42.449,38.914 v2@42.474,38.914 ; v2@42.474,38.911 42.528,38.911 42.839,39.222 43.942,39.222 44.372,39.651 45.33,39.651 45.854,39.127 45.854,36.739 46.855,35.738 52.398,35.738 52.95,35.186 52.95,33.294 53.35,32.894 53.35,30.711 53.151,30.513 v7(53.15,28.424)
  Bottom Layer w0.1: v4(68.475,36.65) v4(68.475,37.15)
  Bottom Layer w0.2: C17.2@68.045,37.15 v4(68.475,37.15) ; v6(68.341,28.116) 68.383,28.116 68.558,27.941 R67.2@70.199,27.941 ; v1(68.475,33.65) 68.475,34.2 C197.2@68.55,34.275 ; C197.2@68.5,34.275 68.525,34.25 C197.2@68.575,34.2 ; C205.2@69.025,35.375 69.1,35.3 69.325,35.3 v1(69.475,35.15) ; C307.1@69.05,34.275 69.175,34.15 v1(69.475,34.15) ; C219.2@70.05,36.475 70.214,36.639 v6@70.464,36.639 ; v6(70.474,36.149) 70.463,36.16 70.463,36.203 70.45,36.215 70.45,36.583 70.464,36.596 v6@70.464,36.639 ; v4(70.475,36.65) v6@70.464,36.639
  Bottom Layer w0.3: R260.2@39.709,39.82 40.684,39.82 40.673,39.81 40.673,39.178 v2@40.663,39.168
  other v1: 70.474,36.149 68.475,36.65 70.475,36.65 68.475,37.15
  other v2: 40.682,39.166
  other v4: 68.475,33.65 69.475,34.15 69.475,35.15 70.474,36.149
  other v6: 68.475,33.65 69.475,34.15 69.475,35.15 68.475,36.65 70.475,36.65 68.475,37.15
  other v7: 52.475,27.699 53.15,27.699 52.475,28.424
  other v9: 68.35,28.125
VDDIO_FB: LNK11.1 U26.17 | length 13.4
  Top Layer w0.15: U26.17@42.568,32.139 43.098,32.139 43.701,31.536 v2(43.713,31.536)
  Top Layer w0.2: LNK11.1@53.998,29.804 v2(53.998,31.539)
  Bottom Layer w0.15: v2@53.996,31.534 v2@53.999,31.537
  Bottom Layer w0.2: v2(43.713,31.536) v2@53.996,31.534
VDDIO_SDCARD: C210.2 C217.1 U14.D10 U26.2 | length 63
  Top Layer w0.21: 36.857,30.012 37.198,30.353 U26.2@37.198,30.769
  Top Layer w0.3: C217.1@35.623,28.519 35.668,28.564 35.957,28.564 36.233,28.84 v2(36.233,28.876)
  Top Layer w0.4: C217.1@35.623,28.459 35.623,28.519 35.623,29.154 36.297,29.829 36.673,29.829 36.857,30.012
  Signal Layer 4 w0.5: v2(46.7,48.75) 46.707,48.757 68.068,48.757 v2(68.075,48.75)
  Bottom Layer w0.2: v6(70.475,37.15) 70.875,37.15 C210.2@70.9,37.125 ; C210.2@70.875,37.096 70.875,38.475
  Bottom Layer w0.5: v2@36.214,28.877 36.775,29.438 36.775,35.501 38.318,37.044 38.318,39.173 38.761,39.616 38.761,40.93 46.581,48.75 v2(46.7,48.75) ; v2(68.075,48.75) 68.3,48.75 69.85,47.2 69.85,43.425 70.875,42.4 70.875,38.475
  other v1: 70.475,37.15
  other v4: 70.475,37.15
VREF+: C248.2 C250.2 R269.2 U14.U2 | length 4.9
  Top Layer w0.075: v2@65.375,30.3 65.782,30.3 65.875,30.392 66.07,30.392 66.316,30.638 66.463,30.638 U14.U2@66.475,30.65
  Bottom Layer w0.2: v2@65.4,30.325 65.4,32.45 R269.2@65.55,32.6 ; v2(65.425,30.25) 65.506,30.25 65.781,30.525 65.875,30.525 C248.2@65.95,30.6 ; C248.2@65.955,30.605 65.96,30.6 66.565,30.6 C250.2@66.57,30.605
pads on no net: U10.A1 U10.A2 U10.A8 U10.A11 U10.A12 U10.AA1 U10.AA2 U10.AA4 U10.AA9 U10.AA11 U10.AA12 U10.AB1 U10.AB2 U10.AB11 U10.AB12 U10.B1 U10.B12 U10.G11 U10.H3 U10.J5 U10.K5 U10.K8 U10.N5 U10.N8 U10.P2 U10.P4 U10.P5 U10.P8 U10.P9 U10.P11 U10.R2 U10.R3 U10.R4 U10.R9 U10.R10 U10.R11 U10.T2 U10.U2 U10.U4 U10.U9 U10.U11 U10.V2 U10.V3 U10.V4 U10.V9 U10.V10 U10.V11 U10.W3 U10.W10 U10.Y2 U10.Y3 U10.Y4 U10.Y9 U10.Y10 U10.Y11 U14.E19 U14.F19 U14.G17 U14.G19 U14.H17 U14.H19 U14.J18 U14.K17 U14.K18 U14.K19 U14.L18 U14.L19 U14.M18 U14.M19 U14.N18 U14.N19 U14.P1 U14.P17 U14.P18 U14.P19 U14.R17 U14.R19 U14.T12 U37.A1 U37.A2 U37.A7 U37.A8 U37.A9 U37.A10 U37.A11 U37.A12 U37.A13 U37.A14 U37.B1 U37.B7 U37.B8 U37.B9 U37.B10 U37.B11 U37.B12 U37.B13 U37.B14 U37.C1 U37.C3 U37.C5 U37.C7 U37.C8 U37.C9 U37.C10 U37.C11 U37.C12 U37.C13 U37.C14 U37.D1 U37.D2 U37.D3 U37.D4 U37.D12 U37.D13 U37.D14 U37.E1 U37.E2 U37.E3 U37.E5 U37.E8 U37.E9 U37.E10 U37.E12 U37.E13 U37.E14 U37.F1 U37.F2 U37.F3 U37.F10 U37.F12 U37.F13 U37.F14 U37.G1 U37.G2 U37.G3 U37.G10 U37.G12 U37.G13 U37.G14 U37.H1 U37.H2 U37.H3 U37.H12 U37.H13 U37.H14 U37.J1 U37.J2 U37.J3 U37.J12 U37.J13 U37.J14 U37.K1 U37.K2 U37.K3 U37.K6 U37.K7 U37.K10 U37.K12 U37.K13 U37.K14 U37.L1 U37.L2 U37.L3 U37.L12 U37.L13 U37.L14 U37.M1 U37.M2 U37.M3 U37.M7 U37.M8 U37.M9 U37.M10 U37.M11 U37.M12 U37.M13 U37.M14 U37.N1 U37.N3 U37.N6 U37.N7 U37.N8 U37.N9 U37.N10 U37.N11 U37.N12 U37.N13 U37.N14 U37.P1 U37.P2 U37.P7 U37.P8 U37.P9 U37.P10 U37.P11 U37.P12 U37.P13 U37.P14
copper on no net: | length 0.4
  Signal Layer 1 w0.1: 73.712,22.092 73.715,22.095
  Signal Layer 2 w0.075: 69.22,45.77 69.225,45.775
  Signal Layer 4 w0.09: 54.67,69.65 54.673,69.647 ; 54.673,69.127 54.75,69.05
  Bottom Layer w0.09: 29.625,93.625 29.8,93.8

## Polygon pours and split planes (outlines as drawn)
5V_STLK on Signal Layer 4 "5V_STLK" (solid, pour order 297): 125,95.201 125,0.3 0,0.3 0,95.201
VDD2_DDR on Signal Layer 4 "VDD_DDR" (solid, remove dead copper, pour order 293): 73.2,42.125 73.2,31.05 74.562,29.687 93.05,29.813 93.05,39.425 84.537,39.425 75.839,48.123 30.252,48.123 25.645,43.516 25.645,36.278 26.317,35.606 27.615,35.606 28.618,36.609 28.618,41.913 29.454,42.75 72.575,42.75
VDDCPU on Signal Layer 4 "VDDCPU" (solid, remove dead copper, pour order 292): 46.237,38.475 69.4,38.475 71.025,36.85 71.025,32.9 73.2,32.9 73.2,42.125 72.687,42.638 40.002,42.638 40.002,42.651 39.116,43.538 30.242,43.538 28.618,41.913 28.618,39.888 28.718,39.988 38.515,39.988 39.454,39.05 39.542,39.138 45.574,39.138
VDDGPU on Signal Layer 4 "VDDGPU" (solid, remove dead copper, pour order 272): 53.029,33.196 55.325,30.9 70.275,30.9 70.275,32.1 70.725,32.1 70.725,33.35 73.25,33.35 73.25,28.075 49.673,28.075 46.8,30.879 46.8,34.699 47.529,35.428 53.029,35.428
3V3 on Signal Layer 4 "3V3_L4" (solid, remove dead copper, pour order 294): 33.955,30.677 32.353,29.075 15.11,29.075 15.11,19.532 37.399,19.532 37.399,30.677
VDDCORE on Signal Layer 4 "VDDCORE" (solid, remove dead copper, pour order 291): 53.144,33.175 55.394,30.925 70.975,30.925 70.975,36.735 69.335,38.375 53.144,38.375
GND on Top Layer "GND_L01_P283" (solid, pour order 283): 0.118,95.007 125.307,95.007 125.307,-0.293 0.468,-0.293
VDDIO on Top Layer "VDDIO" (solid, pour order 280): 41.893,36.909 41.893,38.707 42.428,39.242 42.61,39.242 43.048,38.803 43.048,38.262 42.348,37.562 42.348,36.909
VDDCORE on Top Layer "VDDCORE_TOP" (solid, pour order 278): 51.905,42.834 54.787,39.952 54.787,33.725 54.792,33.72 53.338,33.72 52.793,34.265 52.793,38.966 52.42,39.339 50.773,39.339 46.413,39.339 46.403,42.834
NetL6_1 on Top Layer "NetL13_1" (solid, pour order 282): 44.273,32.002 44.736,31.539 45.998,31.539 45.998,29.239 45.996,29.237 44.699,29.237 44.699,30.861 44.273,31.287
3V3 on Top Layer "3V3" (solid, pour order 281): 23.785,26.687 23.96,26.512 30.308,26.512 31.61,27.814 31.61,28.662 23.986,28.662 23.785,28.462
VDDGPU on Top Layer "VDDGPU_TOP" (solid, pour order 279): 52.501,33.739 52.643,33.881 52.643,36.859 47.923,36.859 47.923,33.739
VDDCPU on Top Layer "VDDCPU_TOP" (solid, pour order 277): 28.71,41.984 28.71,40.137 29.233,39.614 33.648,39.614 33.643,39.619 33.643,41.984
5V_STLK on Top Layer "5V_VIN" (solid, pour order 259): 33.408,33.759 34.065,33.759 34.248,33.942 34.248,33.602 33.765,33.119 33.408,33.119
GND on Signal Layer 3 "GND" (solid, pour order 298): 125,95 125,0 0,0 0,95
1V8 on Signal Layer 3 "1V8_L04_P295" (solid, pour order 295): 66.275,34.3 71.55,34.3 71.55,27.275 73.9,27.275 86.65,27.275 86.65,52.875 76.525,52.875 76.525,49.35 39.4,49.35 39.4,39.55 66.275,39.55
VDDIO on Signal Layer 3 "VDDIO" (solid, remove dead copper, pour order 252): 69.775,35.95 70.025,36.2 70.025,36.9 70.8,36.9 70.8,33.9 70.525,33.9 70.525,26.35 53.129,26.35 51.952,27.527 51.952,29.784 53.344,31.176 63.125,31.176 63.125,34.2 68.275,34.2 68.275,34.3 69.275,34.3 69.275,35.95
GND on Signal Layer 2 "GND_L03_P299" (solid, pour order 299): -0.045,94.712 124.993,94.712 124.993,-0.288 0.304,-0.288
VDDIO on Signal Layer 2 "VDDIO_L03_P258" (solid, pour order 258): 69,37.35 69,37 69.275,36.725 69.65,36.725 69.75,36.825 69.75,37.35 70.675,37.35 70.675,33.35 67.95,33.35 67.95,37.35
GND on Signal Layer 1 "gnd" (solid, pour order 236): -0.171,94.778 125,94.778 125,-0.222 0.003,-0.222
GND on Bottom Layer "GND" (solid, remove dead copper, pour order 257): 0,95.1 125,95.1 125,0.1 0,0.1

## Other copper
Top Layer:
  rectangle net VDD2_DDR: 26.553,31.939 29.523,33.739
  region net GND: 35.798,37.824 35.705,37.824 ccw(c35.705,37.723) 35.633,37.794 35.353,37.514 ccw(c35.425,37.442) 35.323,37.442 35.323,37.114 35.823,37.114 cw(c36.221,37.121) 36.213,37.519 36.473,37.514 ccw(c36.473,37.562) 36.507,37.528 36.603,37.624
  region net 5V_STLK: 36.128,38.663 36.029,38.564 35.673,38.564 cw(c35.673,38.914) 35.323,38.914 35.323,38.964 34.598,38.964 ccw(c34.598,38.889) 34.523,38.889 34.523,38.539 ccw(c34.725,38.536) 34.723,38.334 37.348,38.334 37.748,37.939 38.01,37.939 37.289,38.66 37.023,38.664
  region net 5V_STLK: 44.503,37.919 44.328,37.811 ccw(c44.461,37.612) 44.292,37.781 44.251,37.74 ccw(c44.511,37.481) 44.144,37.481 44.144,37.465 ccw(c44.499,37.465) 44.248,37.214 44.248,35.678 44.247,35.677 44.245,35.69 43.774,35.219 43.168,35.219 43.168,35.484 43.404,35.484 43.878,35.958 43.878,38.486 44.206,38.809 45.223,38.809 45.223,37.919
  pour cut-out: 73,41.85 77.875,46.725 77.875,49.9 78.15,50.175 78.163,50.162 79.37,50.162 79.37,45.905 79.375,45.9 73.725,40.25 73.05,40.25 73,40.3
  pour cut-out: 73.633,39.975 64.815,39.975 64.815,28.1 73.581,28.1 73.578,27.3 93.622,27.3 93.622,40.4 73.635,40.4
  pour cut-out: 78.901,53.292 86.176,53.292 86.176,46.09 78.901,46.09
  region net 5V_STLK: 45.023,37.489 45.173,37.339 45.173,37.089 44.373,37.089 44.373,37.339 44.523,37.489 44.523,37.739 45.023,37.739
  pour cut-out: 46.753,31.014 48.528,31.014 48.528,29.739 47.198,29.739
  pour cut-out: 29.393,31.789 30.453,31.789 30.453,33.889 29.393,33.889
  region net 5V_STLK: 33.773,31.039 33.614,31.039 33.587,31.013 33.546,30.981 33.5,30.954 33.452,30.934 33.401,30.921 33.349,30.914 33.323,30.913 32.823,30.913 32.797,30.914 32.745,30.921 32.694,30.934 32.646,30.954 32.6,30.981 32.559,31.013 32.548,30.589 32.548,30.084 32.273,30.084 32.273,29.444 32.728,29.444 33.497,30.213 33.497,30.323 33.501,30.366 33.511,30.409 33.527,30.449 33.55,30.485 33.578,30.518 33.936,30.876
  pour cut-out: 32.398,30.739 30.448,30.739 30.448,30.164 32.398,30.164
  pour cut-out: 31.698,39.744 31.698,38.684 33.798,38.684 33.798,39.744
  pour cut-out: 38.053,42.364 37.333,42.364 37.333,40.264 38.053,40.264
  pour cut-out: 32.838,29.239 31.778,29.239 31.778,27.139 32.838,27.139
  pour cut-out: 46.343,41.389 45.283,41.389 45.283,39.289 46.343,39.289
  pour cut-out: 47.853,35.589 46.793,35.589 46.793,33.489 47.853,33.489
  pour cut-out: 46.798,31.214 45.998,31.214 45.998,29.114 46.798,29.114
  region net GND: 36.473,37.514 36.138,37.514 36.138,37.524
  region net 5V_STLK: 38.323,37.864 38.298,37.864 37.528,38.634 37.528,38.964 38.168,38.964 38.168,38.744 38.298,38.614 38.298,38.064
  region net GND: 42.819,36.795 42.918,36.795 42.947,36.792 42.976,36.783 43.002,36.769 43.025,36.751 43.043,36.728 43.068,36.694 43.068,36.369 43.168,36.369 43.168,37.069 42.819,37.069
  region net 5V_STLK: 34.148,39.439 34.193,39.484 34.548,39.484 34.548,38.789 34.298,38.789 34.148,38.939 33.898,38.939 33.898,39.439
  region net 5V_STLK: 45.073,39.139 45.223,38.989 45.223,38.739 44.423,38.739 44.423,38.989 44.573,39.139 44.573,39.389 45.073,39.389
  pour cut-out: 23.798,28.912 30.448,28.912 30.448,29.712 23.798,29.712
  pour cut-out: 53.498,30.064 48.528,30.064 48.528,30.714 53.498,30.714
  region net 5V_STLK: 45.093,36.314 45.093,35.459 45.023,35.389 44.898,35.514 44.298,35.514 44.453,35.669 44.453,36.314
  region net 5V_STLK: 44.973,31.989 44.875,32.087 44.875,32.764 45.518,32.764 45.518,32.034 45.473,31.989 45.473,31.739 44.973,31.739
  region net GND: 43.728,34.264 44.178,34.264 44.178,33.964 44.053,33.839 43.878,34.014 43.728,34.014
  region net 5V_STLK: 45.023,35.389 44.448,34.814 43.773,34.814 43.773,34.989 44.298,35.514
  region net NetL5_1: 30.323,34.087 30.548,34.312 31.923,34.312 31.923,32.462 31.4,31.939 31.123,31.939 30.323,31.939
  region net NetL1_1: 38.893,40.414 38.548,40.069 38.093,40.524 38.093,42.214 38.893,42.214
  region net NetL7_1: 33.773,28.489 33.473,28.189 32.698,28.189 32.698,29.089 33.773,30.159
  region net NetL3_1: 34.681,38.184 34.652,38.187 34.623,38.196 34.549,38.228 34.523,38.242 34.501,38.261 34.445,38.319 34.426,38.342 34.412,38.368 34.386,38.433 34.379,38.455 34.356,38.486 34.331,38.506 34.295,38.53 34.249,38.539 33.473,38.539 33.473,37.402
  region net NetL3_1: 33.473,37.114 32.286,38.301 33.386,38.301 33.473,38.214 37.078,38.214 37.318,37.974 35.688,37.974 35.666,37.972 35.646,37.968 35.618,37.959 35.599,37.952 35.573,37.938 35.556,37.927 35.533,37.908 35.239,37.613 35.22,37.591 35.209,37.574 35.2,37.558 35.188,37.529 35.184,37.517 35.179,37.501 35.175,37.481 35.174,37.466 35.172,37.452 35.172,37.114
  region net NetL4_1: 45.423,35.739 45.423,33.739 46.332,33.739 46.332,35.739
  region net NetL2_1: 44.548,40.364 44.548,39.589 44.413,39.589 43.723,38.899 43.723,36.139 43.248,35.664 42.923,35.664 42.923,35.814 43.012,35.814 43.168,35.97 43.348,36.15 43.403,36.233 43.423,36.33 43.423,36.881 43.468,36.989 43.468,37.149 43.407,37.296 43.295,37.408 43.168,37.461 43.148,37.464 43.148,41.241 43.496,41.589 44.413,41.589 44.548,41.454 44.548,41.339
  region net GND: 38.923,45.564 39.073,45.414 39.073,45.164 38.198,45.164 38.198,45.589 38.423,45.814 38.923,45.814
  region net GND: 38.923,45.564 38.773,45.414 38.773,45.164 39.598,45.164 39.598,45.639 39.423,45.814 38.923,45.814
  region net GND: 37.073,45.564 37.223,45.414 37.223,45.164 36.348,45.164 36.348,45.589 36.573,45.814 37.073,45.814
  region net GND: 37.073,45.564 36.923,45.414 36.923,45.164 37.748,45.164 37.748,45.639 37.573,45.814 37.073,45.814
  region net GND: 35.223,45.564 35.073,45.414 35.073,45.164 35.898,45.164 35.898,45.639 35.723,45.814 35.223,45.814
  region net GND: 35.223,45.564 35.373,45.414 35.373,45.164 34.498,45.164 34.498,45.589 34.723,45.814 35.223,45.814
  region net GND: 47.098,44.964 47.293,44.769 47.293,43.914 46.403,43.914 46.403,44.769 46.598,44.964
  region net GND: 48.373,44.964 48.568,44.769 48.568,43.914 47.678,43.914 47.678,44.769 47.873,44.964
  region net GND: 49.648,44.964 49.843,44.769 49.843,43.914 48.953,43.914 48.953,44.769 49.148,44.964
  region net GND: 50.923,44.964 51.118,44.769 51.118,43.914 50.228,43.914 50.228,44.769 50.423,44.964
  region net GND: 30.848,44.012 31.043,43.817 31.043,43.362 30.153,43.362 30.153,43.817 30.348,44.012
  region net GND: 32.148,44.012 32.343,43.817 32.343,43.362 31.453,43.362 31.453,43.817 31.648,44.012
  region net GND: 33.448,44.012 33.643,43.817 33.643,43.362 32.753,43.362 32.753,43.817 32.948,44.012
  region net GND: 24.498,35.439 24.693,35.634 25.473,35.634 25.473,34.744 24.693,34.744 24.498,34.939
  region net GND: 24.498,34.139 24.693,34.334 25.473,34.334 25.473,33.444 24.693,33.444 24.498,33.639
  region net GND: 24.498,32.839 24.693,33.034 25.473,33.034 25.473,32.144 24.693,32.144 24.498,32.339
  region net VDD2_DDR: 27.193,35.754 27.193,35.87 27.546,36.223 27.546,37.354 27.193,37.354 26.553,37.354 26.196,37.354 26.196,36.158 26.553,35.801 26.553,35.377 27.193,35.377
  region net GND: 35.498,39.462 35.695,39.659 36.148,39.659 36.148,38.769 35.691,38.769 35.498,38.962
  region net 5V_STLK: 38.073,39.989 38.168,39.894 38.168,39.589 37.528,39.589 37.528,39.944 37.573,39.989 37.573,40.239 38.073,40.239
  region net GND: 32.823,31.091 32.628,31.286 32.628,31.741 33.518,31.741 33.518,31.286 33.323,31.091
  region net 5V_STLK: 34.148,33.759 34.148,33.539 33.728,33.119 32.048,33.119 32.048,33.664 32.298,33.664 32.393,33.759
  region net GND: 30.973,30.889 31.018,30.844 31.578,30.844 31.623,30.889 31.623,31.484 31.318,31.484 31.223,31.389 30.973,31.389
  region net GND: 24.523,30.937 24.373,30.787 24.373,30.537 25.198,30.537 25.198,31.012 25.023,31.187 24.523,31.187
  region net GND: 24.523,30.937 24.673,30.787 24.673,30.537 23.798,30.537 23.798,30.962 24.023,31.187 24.523,31.187
  region net GND: 26.323,30.937 26.173,30.787 26.173,30.537 26.998,30.537 26.998,31.012 26.823,31.187 26.323,31.187
  region net GND: 26.323,30.937 26.473,30.787 26.473,30.537 25.598,30.537 25.598,30.962 25.823,31.187 26.323,31.187
  region net GND: 28.123,30.937 27.973,30.787 27.973,30.537 28.798,30.537 28.798,31.012 28.623,31.187 28.123,31.187
  region net GND: 28.123,30.937 28.273,30.787 28.273,30.537 27.398,30.537 27.398,30.962 27.623,31.187 28.123,31.187
  region net GND: 29.923,30.937 29.773,30.787 29.773,30.537 30.598,30.537 30.598,31.012 30.423,31.187 29.923,31.187
  region net GND: 29.923,30.937 30.073,30.787 30.073,30.537 29.198,30.537 29.198,30.962 29.423,31.187 29.923,31.187
  region net 5V_STLK: 30.973,30.087 31.623,30.087 31.623,29.444 31.318,29.444 31.223,29.539 30.973,29.539
  region net VDDIO: 52.478,28.974 52.478,28.858 52.125,28.505 52.125,27.374 52.478,27.374 53.118,27.374 53.475,27.374 53.475,28.57 53.118,28.927 53.118,29.351 52.478,29.351
  region net GND: 52.448,38.964 52.643,38.769 52.643,37.914 51.753,37.914 51.753,38.769 51.948,38.964
  region net GND: 51.148,38.964 51.343,38.769 51.343,37.914 50.453,37.914 50.453,38.769 50.648,38.964
  region net GND: 49.848,38.964 50.043,38.769 50.043,37.914 49.153,37.914 49.153,38.769 49.348,38.964
  region net GND: 48.548,38.964 48.743,38.769 48.743,37.914 47.853,37.914 47.853,38.769 48.048,38.964
  region net GND: 47.198,36.464 47.003,36.269 46.148,36.269 46.148,37.159 47.003,37.159 47.198,36.964
  region net GND: 35.173,41.512 35.368,41.317 35.368,40.862 34.478,40.862 34.478,41.317 34.673,41.512
  region net GND: 47.223,38.114 47.028,37.919 46.173,37.919 46.173,38.809 47.028,38.809 47.223,38.614
  region net GND: 47.4,32.514 47.205,32.319 46.898,32.319 46.898,33.209 47.373,33.209 47.568,33.014 47.568,32.514
  region net GND: 53.498,31.437 53.498,32.79 52.098,32.79 52.098,31.437
  region net GND: 51.698,31.437 51.698,32.79 50.298,32.79 50.298,31.437
  region net GND: 49.898,31.437 49.898,32.79 48.498,32.79 48.498,31.437
Signal Layer 1:
  text "2" at 121.175,16.8 h1.2 r90
Signal Layer 2:
  pour cut-out: 71.966,38.795 71.966,43.962 79.041,51.037 84.066,51.037 84.991,50.112 84.991,47.712 84.666,47.387 83.616,47.387 75.048,38.819
  pour cut-out: 73.842,39.775 89.1,39.775 89.1,30.4 73.801,30.4
  text "3" at 121.175,18.05 h1.2 r90
Signal Layer 3:
  text "4" at 121.175,19.3 h1.2 r90
Signal Layer 4:
  text "5" at 121.175,20.55 h1.2 r90
Bottom Layer:
  region: 60.85,16.425
  region: 60.85,16.425
  text "R" at 257.217,60.102 h1.2
  text "2" at 258.744,60.102 h1.2
  text "6" at 259.911,60.087 h1.2
  text "7" at 260.989,60.085 h1.2
  text "0" at 264.831,60.087 h1.2
  text "R" at 265.999,60.102 h1.2
  text "6" at 121.175,21.8 h1.2 r90
Multi-Layer:
  pour cut-out: 119.8,15.425 121.55,15.425 121.55,23.05 119.8,23.05

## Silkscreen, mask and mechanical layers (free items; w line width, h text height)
Top Overlay:
  text "J" at 48.257,80.012 h15
Bottom Overlay:
  lines w0.1: 55.225,72.525 55.225,47.925 76.7,47.925 76.7,72.528 55.225,72.528 ; 69.675,44.8 70.025,44.45 ; 70.025,47.85 70.025,44.45 ; 70.375,44.8 70.025,44.45
  text "J" at 31.1,87.65 h1.2
Top Paste:
  text ".Layer_Name" at 27.423,-26.172 h1.2
  text ".GTP" at 69.118,-26.172 h1.2
Bottom Paste:
  text ".GBP" at 57.907,-26.196 h1.2
  text ".Layer_Name" at 99.221,-26.196 h1.2
Top Solder:
  region: 119.8,15.425 121.55,15.425 121.55,23.05 119.8,23.05
  text ".Layer_Name" at 27.423,-26.172 h1.2
  text ".GTS" at 69.118,-26.172 h1.2
Bottom Solder:
  region: 119.8,15.425 121.55,15.425 121.55,23.05 119.8,23.05
  text ".GBS" at 57.907,-26.196 h1.2
  text ".Layer_Name" at 99.221,-26.196 h1.2
M1-Board Shape:
  the board outline again, w0.1
M14-Top Assembly:
  text ".Layer_Name" at 27.423,-26.172 h1.2
  text ".GM14" at 69.118,-26.172 h1.2
M15-Bottom Assembly:
  text ".GM15" at 57.907,-26.196 h1.2
  text ".Layer_Name" at 99.221,-26.196 h1.2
